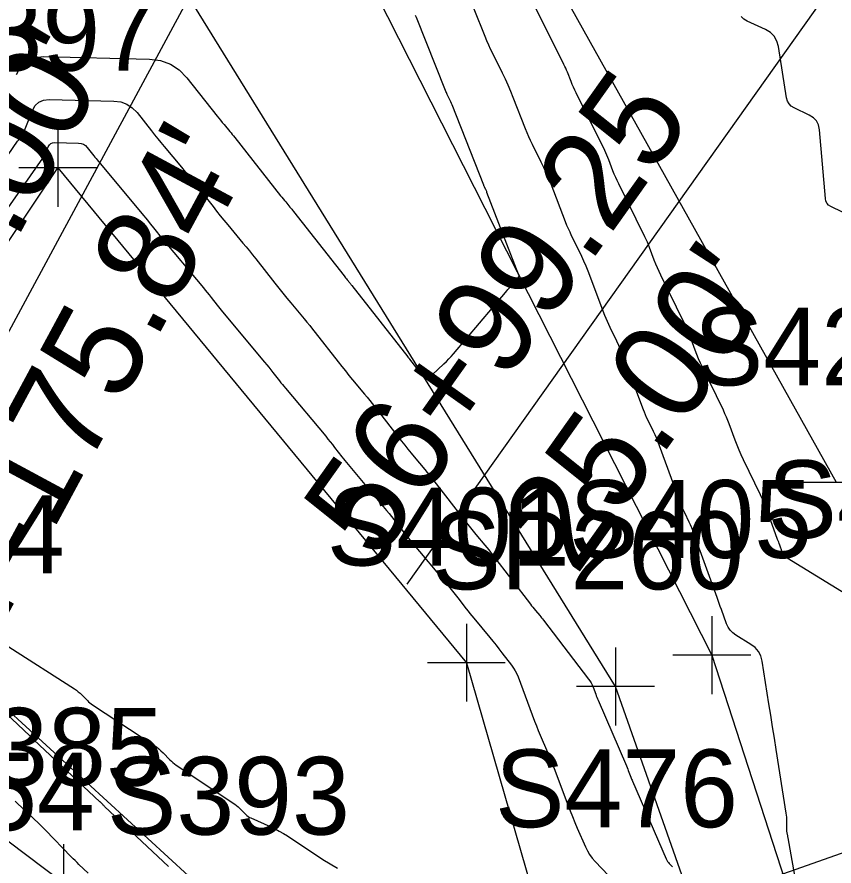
# Model space of a CAD drawing. Extents: x 816928 to 825690, y 436959 to 448212.
# Drawn here: x 818968.86 to 819010.87, y 445066.38 to 445110.04 of the extents above; entities that cross this region are included whole.
import ezdxf

# ---------------------------------------------------------------- set-up
doc = ezdxf.new("R2010")
doc.units = 0
for name, color, linetype in [('SURVEY - CONTOURS - Index with Text', 7, 'Continuous'), ('SURVEY - CONTOURS - Intermediate with optional Text', 7, 'Continuous'), ('SURVEY - DTM - Breaklines', 7, 'Continuous'), ('SURVEY - DTM - Breaklines - Points - Locators', 7, 'Continuous'), ('SURVEY - DTM - Breaklines - Points - Numbers', 7, 'Continuous'), ('SURVEY - NON-TRANSPORTATION - Features', 7, 'Continuous'), ('SURVEY - NON-TRANSPORTATION - Features - Points - Numbers', 7, 'Continuous'), ('SURVEY - PROPERTY - Parcels', 7, 'Continuous'), ('SURVEY - PROPERTY - ROW Lines', 7, 'Continuous'), ('SURVEY - PROPERTY - ROW Lines Text', 7, 'Continuous'), ('SURVEY - PROPERTY - Station and Offset Flags', 7, 'Continuous')]:
    doc.layers.add(name, color=color, linetype=linetype)

msp = doc.modelspace()

# ---------------------------------------------------------------- linework, layer by layer
at = {"layer": 'SURVEY - CONTOURS - Index with Text'}
for points in [[(819011.303, 445099.992), (819010.71, 445100.286), (819010.597, 445100.359), (819010.513, 445100.451), (819010.458, 445100.563), (819010.431, 445100.694), (819010.121, 445104.239), (819010.071, 445104.482), (819009.968, 445104.688), (819009.811, 445104.857), (819009.6, 445104.989), (819008.825, 445105.358), (819008.676, 445105.45), (819008.561, 445105.568), (819008.48, 445105.711), (819008.434, 445105.88), (819008.013, 445108.513), (819007.934, 445108.8), (819007.796, 445109.043), (819007.6, 445109.241), (819007.345, 445109.395), (819006.414, 445109.823), (819006.234, 445109.931), (819006.091, 445110.068)], [(818968.449, 445077.653), (818971.818, 445075.485), (818971.919, 445075.415), (818972.017, 445075.34), (818972.11, 445075.26), (818972.198, 445075.174), (818972.481, 445074.885), (818972.543, 445074.825), (818972.608, 445074.768), (818972.676, 445074.715), (818972.746, 445074.666), (818975.906, 445072.59), (818976.032, 445072.502), (818976.152, 445072.408), (818976.268, 445072.307), (818976.377, 445072.2), (818976.727, 445071.838), (818976.804, 445071.763), (818976.884, 445071.692), (818976.968, 445071.626), (818977.056, 445071.563), (818980.058, 445069.552), (818980.146, 445069.489), (818980.231, 445069.422), (818980.311, 445069.35), (818980.389, 445069.274), (818980.634, 445069.018), (818980.689, 445068.966), (818980.748, 445068.92), (818980.811, 445068.88), (818980.879, 445068.847), (818981.916, 445068.388), (818982.136, 445068.285), (818982.351, 445068.174), (818982.561, 445068.053), (818982.766, 445067.923), (818984.587, 445066.715), (818984.958, 445066.484), (818985.339, 445066.274)], [(818976.651, 445066.358), (818973.37, 445069.441), (818973.345, 445069.465), (818973.321, 445069.489), (818973.296, 445069.513), (818973.272, 445069.537), (818973.194, 445069.618), (818973.178, 445069.635), (818973.161, 445069.652), (818973.143, 445069.669), (818973.126, 445069.685), (818969.737, 445072.867), (818969.716, 445072.887), (818969.695, 445072.908), (818969.674, 445072.928), (818969.653, 445072.949), (818969.586, 445073.018), (818969.571, 445073.033), (818969.556, 445073.047), (818969.542, 445073.061), (818969.527, 445073.076), (818966.137, 445076.255)]]:
    msp.add_lwpolyline(points, dxfattribs=at)
at = {"layer": 'SURVEY - CONTOURS - Intermediate with optional Text'}
for points in [[(819014.498, 445078.506), (819008.47, 445082.21), (819008.382, 445082.274), (819008.308, 445082.35), (819008.249, 445082.438), (819008.204, 445082.537), (819008.08, 445082.88), (819008.054, 445082.953), (819008.027, 445083.027), (819008, 445083.1), (819007.974, 445083.173), (819007.525, 445084.417), (819007.425, 445084.682), (819007.319, 445084.944), (819007.206, 445085.203), (819007.086, 445085.46), (819006.217, 445087.264), (819006.102, 445087.512), (819005.992, 445087.761), (819005.889, 445088.014), (819005.792, 445088.269), (819005.483, 445089.107), (819005.415, 445089.285), (819005.342, 445089.462), (819005.265, 445089.637), (819005.184, 445089.809), (819004.109, 445092.023), (819004.006, 445092.242), (819003.909, 445092.462), (819003.816, 445092.685), (819003.728, 445092.911), (819003.451, 445093.65), (819003.39, 445093.808), (819003.325, 445093.964), (819003.256, 445094.118), (819003.184, 445094.271), (819001.97, 445096.752), (819001.879, 445096.944), (819001.793, 445097.138), (819001.71, 445097.333), (819001.633, 445097.53), (819001.386, 445098.178), (819001.331, 445098.317), (819001.274, 445098.453), (819001.213, 445098.589), (819001.149, 445098.723), (818999.803, 445101.455), (818999.723, 445101.622), (818999.648, 445101.79), (818999.575, 445101.959), (818999.507, 445102.13), (818999.289, 445102.692), (818999.241, 445102.812), (818999.191, 445102.931), (818999.138, 445103.048), (818999.082, 445103.165), (818997.61, 445106.134), (818997.541, 445106.276), (818997.476, 445106.42), (818997.413, 445106.565), (818997.354, 445106.712), (818997.165, 445107.193), (818997.123, 445107.296), (818997.079, 445107.397), (818997.033, 445107.498), (818996.985, 445107.598), (818995.393, 445110.79)], [(819009.356, 445063.078), (819008.514, 445067.821), (819008.506, 445067.861), (819008.499, 445067.901), (819008.491, 445067.94), (819008.483, 445067.98), (819008.456, 445068.108), (819008.451, 445068.136), (819008.447, 445068.164), (819008.445, 445068.192), (819008.445, 445068.22), (819008.449, 445068.692), (819008.448, 445068.793), (819008.443, 445068.894), (819008.433, 445068.995), (819008.42, 445069.095), (819007.899, 445072.361), (819007.805, 445072.951), (819007.711, 445073.541), (819007.617, 445074.131), (819007.523, 445074.721), (819007.173, 445076.917), (819007.104, 445077.179), (819006.986, 445077.409), (819006.82, 445077.605), (819006.604, 445077.769), (819005.819, 445078.251), (819005.664, 445078.365), (819005.534, 445078.499), (819005.429, 445078.654), (819005.349, 445078.829), (819005.084, 445079.562), (819005.027, 445079.719), (819004.971, 445079.877), (819004.914, 445080.034), (819004.857, 445080.191), (819003.672, 445083.472), (819003.615, 445083.623), (819003.555, 445083.772), (819003.491, 445083.92), (819003.423, 445084.066), (819003.194, 445084.54), (819003.146, 445084.642), (819003.101, 445084.746), (819003.058, 445084.85), (819003.018, 445084.955), (819001.904, 445087.981), (819001.832, 445088.169), (819001.755, 445088.356), (819001.674, 445088.541), (819001.588, 445088.724), (819001.299, 445089.319), (819001.239, 445089.447), (819001.181, 445089.576), (819001.127, 445089.707), (819001.076, 445089.839), (819000.087, 445092.476), (819000, 445092.7), (818999.908, 445092.923), (818999.81, 445093.143), (818999.707, 445093.36), (818999.361, 445094.067), (818999.288, 445094.22), (818999.22, 445094.373), (818999.154, 445094.529), (818999.092, 445094.686), (818998.226, 445096.959), (818998.124, 445097.217), (818998.017, 445097.472), (818997.903, 445097.725), (818997.783, 445097.975), (818997.383, 445098.788), (818997.299, 445098.963), (818997.219, 445099.14), (818997.143, 445099.319), (818997.071, 445099.499), (818996.323, 445101.431), (818996.208, 445101.721), (818996.085, 445102.007), (818995.957, 445102.291), (818995.821, 445102.571), (818995.369, 445103.484), (818995.274, 445103.68), (818995.184, 445103.879), (818995.098, 445104.079), (818995.016, 445104.281), (818994.383, 445105.893), (818994.254, 445106.212), (818994.117, 445106.528), (818993.974, 445106.841), (818993.824, 445107.15), (818993.322, 445108.156), (818993.217, 445108.373), (818993.117, 445108.592), (818993.021, 445108.812), (818992.929, 445109.035), (818992.37, 445110.44)], [(818968.834, 445107.078), (818969.065, 445107.493), (818969.376, 445107.786), (818969.768, 445107.956), (818970.24, 445108.005), (818975.67, 445107.871), (818976.238, 445107.799), (818976.75, 445107.614), (818977.205, 445107.316), (818977.603, 445106.905), (818979.154, 445104.942), (818979.243, 445104.832), (818979.331, 445104.722), (818979.421, 445104.612), (818979.511, 445104.503), (818979.808, 445104.149), (818979.871, 445104.072), (818979.934, 445103.996), (818979.996, 445103.919), (818980.057, 445103.841), (818982.416, 445100.847), (818982.481, 445100.766), (818982.547, 445100.685), (818982.612, 445100.604), (818982.679, 445100.524), (818982.897, 445100.263), (818982.943, 445100.207), (818982.99, 445100.15), (818983.035, 445100.094), (818983.08, 445100.036), (818985.684, 445096.72), (818985.723, 445096.671), (818985.762, 445096.623), (818985.801, 445096.575), (818985.841, 445096.527), (818985.971, 445096.371), (818985.999, 445096.337), (818986.026, 445096.304), (818986.053, 445096.27), (818986.08, 445096.235), (818988.958, 445092.554), (818988.968, 445092.543), (818988.977, 445092.531), (818988.986, 445092.52), (818988.996, 445092.508), (818989.027, 445092.471), (818989.033, 445092.463), (818989.04, 445092.455), (818989.046, 445092.447), (818989.053, 445092.439), (818989.647, 445091.676), (818989.777, 445091.55), (818989.913, 445091.501), (818990.056, 445091.528), (818990.205, 445091.63), (818990.819, 445092.199), (818990.949, 445092.323), (818991.075, 445092.45), (818991.196, 445092.582), (818991.314, 445092.717), (818993.98, 445095.872), (818994.044, 445095.948), (818994.109, 445096.023), (818994.174, 445096.097), (818994.241, 445096.171), (818994.501, 445096.46), (818994.525, 445096.488), (818994.549, 445096.517), (818994.572, 445096.546), (818994.593, 445096.576), (818994.664, 445096.675), (818994.676, 445096.696), (818994.682, 445096.719), (818994.681, 445096.742), (818994.675, 445096.766), (818993.029, 445101.018), (818993.014, 445101.055), (818992.999, 445101.092), (818992.982, 445101.128), (818992.965, 445101.164), (818992.906, 445101.282), (818992.894, 445101.307), (818992.883, 445101.333), (818992.871, 445101.359), (818992.861, 445101.385), (818991.237, 445105.52), (818991.207, 445105.594), (818991.175, 445105.667), (818991.142, 445105.74), (818991.107, 445105.812), (818990.99, 445106.046), (818990.966, 445106.097), (818990.943, 445106.147), (818990.92, 445106.199), (818990.899, 445106.251), (818989.403, 445110.01), (818989.358, 445110.119)], [(818967.881, 445102.192), (818968.89, 445103.644), (818968.909, 445103.669), (818968.929, 445103.692), (818968.951, 445103.713), (818968.976, 445103.733), (818969.058, 445103.793), (818969.074, 445103.807), (818969.088, 445103.823), (818969.1, 445103.84), (818969.109, 445103.86), (818969.655, 445105.223), (818969.796, 445105.477), (818969.987, 445105.657), (818970.228, 445105.761), (818970.518, 445105.791), (818973.851, 445105.709), (818974.2, 445105.665), (818974.514, 445105.552), (818974.793, 445105.369), (818975.038, 445105.116), (818975.78, 445104.177), (818975.94, 445103.977), (818976.101, 445103.777), (818976.263, 445103.579), (818976.427, 445103.381), (818977.323, 445102.309), (818977.514, 445102.079), (818977.703, 445101.847), (818977.891, 445101.614), (818978.077, 445101.38), (818978.942, 445100.282), (818979.128, 445100.047), (818979.316, 445099.814), (818979.506, 445099.582), (818979.697, 445099.352), (818980.483, 445098.411), (818980.65, 445098.209), (818980.816, 445098.006), (818980.981, 445097.801), (818981.144, 445097.595), (818982.126, 445096.344), (818982.328, 445096.089), (818982.532, 445095.835), (818982.738, 445095.583), (818982.945, 445095.332), (818983.627, 445094.516), (818983.773, 445094.34), (818983.917, 445094.164), (818984.059, 445093.986), (818984.201, 445093.807), (818985.379, 445092.299), (818985.562, 445092.067), (818985.747, 445091.837), (818985.933, 445091.608), (818986.122, 445091.38), (818986.74, 445090.64), (818986.872, 445090.48), (818987.003, 445090.32), (818987.132, 445090.159), (818987.259, 445089.996), (818988.638, 445088.225), (818988.799, 445088.019), (818988.962, 445087.816), (818989.126, 445087.613), (818989.293, 445087.412), (818989.839, 445086.758), (818989.955, 445086.617), (818990.071, 445086.475), (818990.184, 445086.333), (818990.297, 445086.189), (818991.903, 445084.114), (818992.039, 445083.939), (818992.177, 445083.766), (818992.316, 445083.595), (818992.457, 445083.424), (818992.921, 445082.869), (818993.019, 445082.75), (818993.117, 445082.629), (818993.213, 445082.508), (818993.308, 445082.386), (818995.261, 445079.847), (818995.326, 445079.764), (818995.391, 445079.681), (818995.457, 445079.6), (818995.524, 445079.519), (818995.745, 445079.255), (818995.792, 445079.198), (818995.838, 445079.141), (818995.883, 445079.083), (818995.929, 445079.025), (818998.252, 445075.993), (818998.32, 445075.896), (818998.382, 445075.794), (818998.435, 445075.689), (818998.481, 445075.579), (818998.618, 445075.213), (818998.647, 445075.135), (818998.678, 445075.057), (818998.71, 445074.98), (818998.742, 445074.903), (819000.201, 445071.52), (819000.234, 445071.443), (819000.266, 445071.365), (819000.297, 445071.287), (819000.328, 445071.208), (819000.425, 445070.951), (819000.446, 445070.896), (819000.467, 445070.841), (819000.49, 445070.787), (819000.513, 445070.732), (819002.244, 445066.743), (819002.276, 445066.678), (819002.313, 445066.617), (819002.355, 445066.559), (819002.403, 445066.505), (819002.566, 445066.333)], [(818968.288, 445100.042), (818970.191, 445102.781), (818970.198, 445102.79), (818970.206, 445102.799), (818970.214, 445102.807), (818970.223, 445102.814), (818970.254, 445102.836), (818970.26, 445102.841), (818970.265, 445102.847), (818970.269, 445102.854), (818970.273, 445102.861), (818970.475, 445103.367), (818970.528, 445103.461), (818970.599, 445103.528), (818970.688, 445103.567), (818970.795, 445103.578), (818972.032, 445103.547), (818972.162, 445103.531), (818972.278, 445103.489), (818972.382, 445103.421), (818972.472, 445103.327), (818972.748, 445102.979), (818972.807, 445102.904), (818972.867, 445102.83), (818972.927, 445102.757), (818972.988, 445102.683), (818975.291, 445099.927), (818975.384, 445099.815), (818975.477, 445099.702), (818975.568, 445099.588), (818975.659, 445099.474), (818975.954, 445099.1), (818976.017, 445099.02), (818976.081, 445098.94), (818976.146, 445098.861), (818976.211, 445098.782), (818978.447, 445096.107), (818978.547, 445095.986), (818978.646, 445095.864), (818978.745, 445095.742), (818978.842, 445095.618), (818979.159, 445095.215), (818979.227, 445095.129), (818979.296, 445095.043), (818979.366, 445094.958), (818979.436, 445094.873), (818981.595, 445092.288), (818981.703, 445092.157), (818981.811, 445092.026), (818981.917, 445091.894), (818982.022, 445091.76), (818982.363, 445091.324), (818982.437, 445091.23), (818982.511, 445091.138), (818982.586, 445091.046), (818982.662, 445090.954), (818984.735, 445088.472), (818984.852, 445088.33), (818984.968, 445088.187), (818985.083, 445088.044), (818985.197, 445087.899), (818985.566, 445087.425), (818985.645, 445087.323), (818985.726, 445087.223), (818985.807, 445087.123), (818985.889, 445087.024), (818987.864, 445084.658), (818987.992, 445084.504), (818988.118, 445084.348), (818988.243, 445084.191), (818988.366, 445084.033), (818988.767, 445083.516), (818988.853, 445083.405), (818988.941, 445083.296), (818989.029, 445083.187), (818989.119, 445083.079), (818990.981, 445080.847), (818991.121, 445080.678), (818991.259, 445080.508), (818991.395, 445080.336), (818991.529, 445080.163), (818991.966, 445079.595), (818992.061, 445079.474), (818992.156, 445079.354), (818992.253, 445079.234), (818992.35, 445079.116), (818993.178, 445078.124), (818993.336, 445077.932), (818993.493, 445077.739), (818993.647, 445077.543), (818993.8, 445077.346), (818994.295, 445076.7), (818994.395, 445076.559), (818994.484, 445076.411), (818994.562, 445076.257), (818994.629, 445076.097), (818995.477, 445073.831), (818995.57, 445073.587), (818995.666, 445073.344), (818995.765, 445073.102), (818995.867, 445072.862), (818996.206, 445072.077), (818996.277, 445071.909), (818996.347, 445071.74), (818996.414, 445071.57), (818996.48, 445071.399), (818997.187, 445069.524), (818997.303, 445069.222), (818997.422, 445068.921), (818997.546, 445068.622), (818997.673, 445068.325), (818998.093, 445067.355), (818998.192, 445067.153), (818998.307, 445066.962), (818998.438, 445066.781), (818998.586, 445066.612), (819001.025, 445064.055)], [(818972.528, 445066.01), (818972.051, 445066.458), (818971.95, 445066.554), (818971.849, 445066.652), (818971.75, 445066.751), (818971.652, 445066.851), (818970.33, 445068.217), (818970.14, 445068.411), (818969.949, 445068.602), (818969.755, 445068.79), (818969.559, 445068.977), (818968.914, 445069.582), (818968.777, 445069.712)]]:
    msp.add_lwpolyline(points, dxfattribs=at)
at = {"layer": 'SURVEY - DTM - Breaklines'}
for points in [[(819024.527, 445056.15), (819018.943, 445074.238), (819023.696, 445085.404), (819011.002, 445086.093), (818989.501, 445124.57), (818993.883, 445133.462)], [(818981.248, 445123.206), (819004.59, 445077.222), (819024.585, 445015.565), (819030.411, 444974.963), (819021.079, 445014.732), (818999.64, 445075.605), (818976.669, 445112.741)], [(818980.825, 445062.99), (818966.168, 445076.431), (818959.397, 445078.359), (818957.421, 445082.085), (818970.959, 445102.272), (818991.969, 445076.829), (818999.493, 445050.72)], [(818948.142, 445082.95), (818971.253, 445065.506), (818976.595, 445052.8), (818975.731, 445043.247), (818942.824, 445025.275), (818970.496, 445043.876), (818971.261, 445052.107), (818966.093, 445063.21), (818943.888, 445080.247)]]:
    msp.add_lwpolyline(points, dxfattribs=at)
at = {"layer": 'SURVEY - DTM - Breaklines - Points - Locators'}
for p, q in [((818970.959, 445104.272), (818970.959, 445100.272)), ((818972.959, 445102.272), (818968.959, 445102.272)), ((819013.002, 445086.093), (819009.002, 445086.093)), ((818991.969, 445078.829), (818991.969, 445074.829)), ((819004.59, 445079.222), (819004.59, 445075.222)), ((818999.64, 445077.605), (818999.64, 445073.605)), ((819006.59, 445077.222), (819002.59, 445077.222)), ((818993.969, 445076.829), (818989.969, 445076.829)), ((819001.64, 445075.605), (818997.64, 445075.605)), ((818971.253, 445067.506), (818971.253, 445063.506))]:
    msp.add_line(p, q, dxfattribs=at)
at = {"layer": 'SURVEY - NON-TRANSPORTATION - Features'}
msp.add_lwpolyline([(819140.689, 445080.529), (819097.737, 445097.538), (819000.89, 445063.371), (818928.914, 445024.247)], dxfattribs=at)
at = {"layer": 'SURVEY - PROPERTY - Parcels'}
msp.add_arc((819561.099, 444735.998), 713, 144.598464, 158.728454, dxfattribs=at)
at = {"layer": 'SURVEY - PROPERTY - ROW Lines'}
msp.add_arc((819561.099, 444735.998), 713, 144.598464, 158.728454, dxfattribs=at)
msp.add_arc((819561.099, 444735.998), 713, 144.598464, 158.728454, dxfattribs=at)
at = {"layer": 'SURVEY - PROPERTY - ROW Lines Text'}
msp.add_line((818980.831, 445116.843), (818960.992, 445080.056), dxfattribs=at)
at = {"layer": 'SURVEY - PROPERTY - Station and Offset Flags'}
msp.add_line((819010.842, 445111.728), (818988.909, 445080.867), dxfattribs=at)

# ---------------------------------------------------------------- texts
at = {"layer": 'SURVEY - DTM - Breaklines - Points - Numbers'}
for s, p in [('S397', (818963.623, 445107.272)), ('S424', (819003.666, 445091.093)), ('S421', (819007.455, 445083.237)), ('S405', (818997.254, 445082.222)), ('S401', (818984.79, 445081.829)), ('S394', (818958.832, 445081.431)), ('SP260', (818990.179, 445080.605)), ('S385', (818963.917, 445070.506)), ('SP254', (818956.805, 445068.21)), ('S393', (818973.489, 445067.99))]:
    msp.add_text(s, height=4, dxfattribs=at).set_placement(p)
at = {"layer": 'SURVEY - NON-TRANSPORTATION - Features - Points - Numbers'}
msp.add_text('S476', height=4, dxfattribs=at).set_placement((818993.444, 445068.371))
at = {"layer": 'SURVEY - PROPERTY - ROW Lines Text'}
for s, p in [("R=713.00'", (818959.343, 445080.946)), ("L=175.84'", (818967.044, 445076.793))]:
    msp.add_text(s, height=5, rotation=61.6635, dxfattribs=at).set_placement(p)
at = {"layer": 'SURVEY - PROPERTY - Station and Offset Flags'}
for s, p in [('56+99.25', (818987.382, 445081.954)), ("25.00'", (818997.614, 445081.248))]:
    msp.add_text(s, height=5, rotation=54.5985, dxfattribs=at).set_placement(p)

doc.saveas('drawing.dxf')
